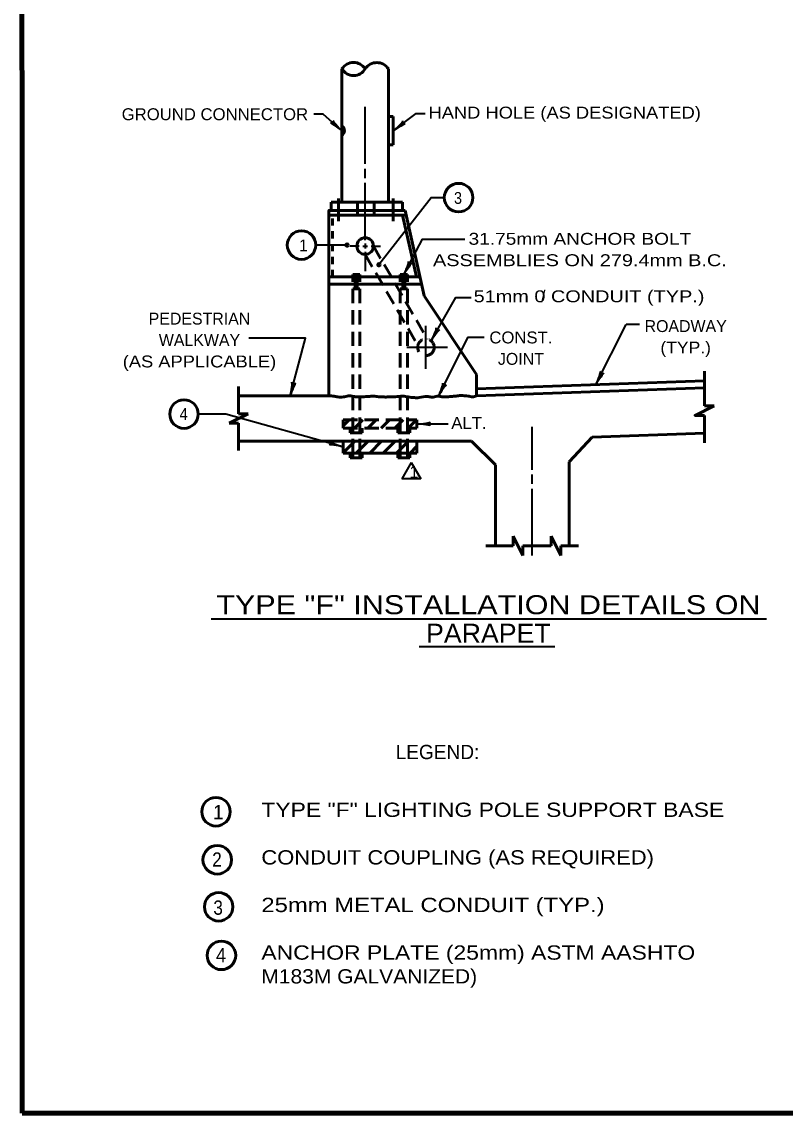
# Model space of a CAD drawing. Extents: x -40 to 816, y -10 to 535.
# Drawn here: x 17.6 to 210.2, y 2 to 277.2 of the extents above; entities that cross this region are included whole.
import ezdxf
from ezdxf.enums import TextEntityAlignment as Align

# ---------------------------------------------------------------- set-up
doc = ezdxf.new("R2010")
doc.units = 0
doc.header["$LTSCALE"] = 1.2
doc.linetypes.add('MEDIUM_DASHED', pattern=[4.5, 3, -1.5])
doc.linetypes.add('SHORT_DASHED', pattern=[2.7, 1.5, -1.2])
doc.layers.add('1', color=7, linetype='Continuous', lineweight=53)

msp = doc.modelspace()

# ---------------------------------------------------------------- hatches: boundary and pattern name
at = {"layer": '1'}
for points in [[(99.956, 220.934, 1), (99.356, 220.934, 1)], [(107.993, 215.956, 1), (107.393, 215.956, 1)]]:
    msp.add_hatch(color=256, dxfattribs=at).paths.add_polyline_path(points)

# ---------------------------------------------------------------- linework, layer by layer
for p, q in [((98.368, 265.381), (98.368, 231.781)), ((110.068, 265.381), (110.068, 231.781)), ((110.068, 253.381), (111.268, 253.381)), ((111.268, 253.381), (111.268, 246.181)), ((110.068, 246.181), (111.268, 246.181)), ((95.668, 231.781), (113.668, 231.781)), ((95.668, 231.781), (95.668, 229.681)), ((97.468, 232.681), (97.468, 226.981)), ((111.268, 232.681), (111.268, 226.981)), ((113.668, 231.781), (113.668, 229.681)), ((95.068, 228.481), (114.539, 228.481)), ((102.268, 229.681), (102.268, 228.481)), ((106.468, 229.681), (106.468, 228.481)), ((113.616, 228.481), (117.138, 212.881)), ((114.268, 229.681), (119.128, 208.155)), ((95.068, 212.881), (118.061, 212.881)), ((101.368, 212.281), (102.568, 212.281)), ((101.668, 213.181), (102.268, 213.181)), ((101.668, 212.581), (102.268, 212.581)), ((101.668, 211.981), (102.268, 211.981)), ((113.368, 212.281), (114.568, 212.281)), ((113.668, 213.181), (114.268, 213.181)), ((113.668, 212.581), (114.268, 212.581)), ((113.668, 211.981), (114.268, 211.981)), ((95.068, 211.081), (118.468, 211.081)), ((101.068, 209.881), (102.868, 209.881)), ((101.368, 211.681), (102.568, 211.681)), ((101.368, 210.481), (102.568, 210.481)), ((101.668, 211.381), (102.268, 211.381)), ((101.668, 210.781), (102.268, 210.781)), ((101.668, 210.181), (102.268, 210.181)), ((113.068, 209.881), (114.868, 209.881)), ((113.368, 211.681), (114.568, 211.681)), ((113.368, 210.481), (114.568, 210.481)), ((113.668, 211.381), (114.268, 211.381)), ((113.668, 210.781), (114.268, 210.781)), ((113.668, 210.181), (114.268, 210.181)), ((119.128, 208.155), (132.268, 188.281)), ((132.268, 182.881), (132.268, 188.281)), ((189.833, 184.891), (189.833, 189.092)), ((72.268, 185.281), (72.268, 178.381)), ((132.268, 184.682), (189.833, 186.692)), ((132.268, 182.881), (189.833, 184.891)), ((189.833, 180.388), (189.833, 184.891)), ((192.233, 180.388), (189.833, 180.388)), ((69.868, 175.981), (74.668, 178.381)), ((74.668, 178.381), (72.268, 178.381)), ((98.668, 175.354), (100.195, 176.881)), ((101.489, 174.781), (103.589, 176.881)), ((104.883, 174.781), (106.983, 176.881)), ((108.277, 174.781), (110.377, 176.881)), ((111.671, 174.781), (113.771, 176.881)), ((115.065, 174.781), (117.165, 176.881)), ((72.268, 175.981), (69.868, 175.981)), ((72.268, 175.981), (72.268, 169.081)), ((161.448, 172.493), (189.833, 173.484)), ((72.268, 171.481), (131.068, 171.481)), ((98.668, 171.481), (98.668, 168.481)), ((98.668, 168.566), (101.583, 171.481)), ((101.977, 168.481), (104.977, 171.481)), ((105.371, 168.481), (108.371, 171.481)), ((108.765, 168.481), (111.765, 171.481)), ((112.159, 168.481), (115.159, 171.481)), ((117.268, 171.481), (117.268, 168.481)), ((131.068, 171.481), (137.068, 165.481)), ((161.448, 172.493), (155.661, 166.287)), ((98.668, 168.481), (117.268, 168.481)), ((100.468, 168.481), (100.468, 167.281)), ((101.068, 168.481), (101.068, 167.281)), ((102.868, 168.481), (102.868, 167.281)), ((103.468, 168.481), (103.468, 167.281)), ((112.468, 168.481), (112.468, 167.281)), ((113.068, 168.481), (113.068, 167.281)), ((114.868, 168.481), (114.868, 167.281)), ((115.468, 168.481), (115.468, 167.281)), ((115.553, 168.481), (117.268, 170.195)), ((100.468, 167.281), (103.468, 167.281)), ((112.468, 167.281), (115.468, 167.281)), ((137.068, 165.481), (137.068, 145.081)), ((155.661, 166.287), (155.661, 145.081)), ((141.564, 147.481), (141.564, 145.081)), ((141.564, 147.481), (143.964, 142.681)), ((151.164, 145.081), (151.164, 147.481)), ((151.164, 147.481), (153.564, 142.681)), ((134.668, 145.081), (141.564, 145.081)), ((143.964, 145.081), (143.964, 142.681)), ((153.564, 142.681), (153.564, 145.081)), ((153.564, 145.081), (158.061, 145.081))]:
    msp.add_line(p, q, dxfattribs=at)
at = {"layer": '1', "lineweight": 35}
for p, q in [((104.218, 241.381), (104.218, 255.781)), ((104.218, 237.781), (104.218, 240.181)), ((104.218, 222.181), (104.218, 236.581)), ((99.656, 220.934), (91.756, 220.923)), ((102.718, 220.681), (100.318, 220.681)), ((103.618, 220.681), (104.818, 220.681)), ((104.218, 221.281), (104.218, 220.081)), ((162.446, 185.736), (170.051, 200.9)), ((173.452, 200.9), (170.051, 200.9)), ((117.268, 175.831), (125.171, 175.831)), ((146.364, 164.281), (146.364, 175.081)), ((115.847, 166.117), (113.447, 161.96)), ((115.847, 166.117), (118.247, 161.96)), ((146.364, 160.681), (146.364, 163.081)), ((118.247, 161.96), (113.447, 161.96)), ((146.364, 142.681), (146.364, 159.481))]:
    msp.add_line(p, q, dxfattribs=at)
at = {"layer": '1', "linetype": 'SHORT_DASHED'}
for p, q in [((102.268, 231.781), (102.268, 229.681)), ((106.468, 231.781), (106.468, 229.681)), ((95.968, 212.881), (95.968, 228.481))]:
    msp.add_line(p, q, dxfattribs=at)
at = {"layer": '1', "linetype": 'MEDIUM_DASHED'}
for p, q in [((106.318, 220.681), (119.879, 197.215)), ((104.218, 218.581), (117.503, 195.592)), ((101.068, 168.481), (101.068, 213.481)), ((101.068, 213.481), (102.868, 213.481)), ((102.868, 168.481), (102.868, 213.481)), ((113.068, 168.481), (113.068, 213.481)), ((113.068, 213.481), (114.868, 213.481)), ((113.068, 212.881), (114.868, 212.881)), ((114.868, 168.481), (114.868, 213.481)), ((113.068, 211.081), (114.868, 211.081)), ((98.668, 176.881), (117.268, 176.881)), ((98.668, 176.881), (98.668, 174.781)), ((117.268, 176.881), (117.268, 174.781)), ((98.668, 174.781), (117.268, 174.781)), ((100.468, 173.581), (100.468, 174.781)), ((100.468, 173.581), (103.468, 173.581)), ((103.468, 173.581), (103.468, 174.781)), ((112.468, 173.581), (112.468, 174.781)), ((112.468, 173.581), (115.468, 173.581)), ((115.468, 173.581), (115.468, 174.781))]:
    msp.add_line(p, q, dxfattribs=at)
at = {"layer": '1', "lineweight": 40}
for p, q in [((65.365, 126.637), (205.457, 126.637)), ((117.867, 119.737), (152.044, 119.737))]:
    msp.add_line(p, q, dxfattribs=at)
at = {"layer": '1', "lineweight": 158}
msp.add_line((809.296, 2.017), (17.696, 2.017), dxfattribs=at)
msp.add_lwpolyline([(809.296, 528.117), (17.596, 528.017), (17.696, 2.017)], dxfattribs=at)
at = {"layer": '1', "lineweight": 35}
for points in [[(98.368, 249.74), (93.63, 253.914), (91.242, 253.914)], [(111.268, 249.728), (117.125, 254.136), (119.347, 254.136)], [(107.635, 215.986), (120.873, 232.891), (124.184, 232.891)], [(105.718, 220.681), (106.318, 220.681), (108.118, 220.681)], [(113.975, 213.481), (118.714, 222.437), (129.397, 222.437)], [(104.218, 219.181), (104.218, 218.581), (104.218, 214.381)], [(120.874, 196.774), (127.086, 207.723), (130.964, 207.723)], [(119.554, 189.74), (119.554, 197.24), (119.554, 200.541)], [(85.307, 182.881), (89.155, 197.409), (74.908, 197.409)], [(122.722, 182.812), (130.207, 197.693), (134.275, 197.693)], [(114.754, 195.141), (117.454, 195.141), (124.954, 195.141)], [(98.569, 170.027), (69.074, 178.308), (62.116, 178.308)]]:
    msp.add_lwpolyline(points, dxfattribs=at)
at = {"layer": '1'}
for points in [[(72.268, 182.881), (95.068, 182.881), (95.068, 229.681), (114.268, 229.681)], [(189.833, 177.988), (187.433, 177.988), (192.233, 180.388)], [(189.833, 171.084), (189.833, 173.484), (189.833, 177.988)], [(143.964, 145.081), (146.364, 145.081), (151.164, 145.081)]]:
    msp.add_lwpolyline(points, dxfattribs=at)
for centre, radius in [((127.784, 232.891), 3.6), ((88.156, 220.923), 3.6), ((99.656, 220.934), 0.3), ((104.218, 220.681), 2.1), ((107.693, 215.956), 0.3), ((58.516, 178.308), 3.6), ((66.582, 78.028), 3.6), ((66.905, 65.909), 3.6), ((67.254, 54.052), 3.6), ((67.954, 41.808), 3.6)]:
    msp.add_circle(centre, radius, dxfattribs=at)
at = {"layer": '1', "linetype": 'MEDIUM_DASHED'}
msp.add_circle((119.554, 195.141), 2.1, dxfattribs=at)
at = {"layer": '1'}
for centre, radius, start, end in [((101.293, 263.531), 3.461, 32.30565, 147.69435), ((101.293, 267.057), 3.381, 210.08876, 329.91124), ((107.143, 263.429), 3.516, 33.70919, 146.29081), ((97.468, 249.781), 1.5, 306.8699, 53.1301)]:
    msp.add_arc(centre, radius, start, end, dxfattribs=at)
at = {"layer": '1', "lineweight": 40}
for centre, major_axis, ratio, start_param, end_param in [((97.166, 250.356), (1.732, -1.276), 0.122415, 0.8963533, 3.1415927), ((97.527, 250.819), (-1.442, 1.552), 0.07063, 6.2823074, 8.5597026), ((112.114, 250.78), (-1.599, -1.438), 0.122415, 0.8963533, 3.1415927), ((112.495, 250.333), (1.811, 1.099), 0.07063, 6.2823074, 8.5597026), ((114.294, 214.793), (-0.837, -1.982), 0.122415, 0.8963533, 3.1415927), ((114.828, 214.551), (1.172, 1.764), 0.07063, 6.2823074, 8.5597026), ((121.231, 198.077), (-0.894, -1.956), 0.122415, 0.8963533, 3.1415927), ((121.758, 197.818), (1.223, 1.729), 0.07063, 6.2823074, 8.5597026), ((162.737, 187.055), (-0.793, -1.999), 0.122415, 0.8963533, 3.1415927), ((163.276, 186.824), (-1.133, -1.79), 0.07063, 3.1407148, 5.41811), ((85.322, 184.232), (-0.367, -2.119), 0.122415, 0.8963533, 3.1415927), ((85.897, 184.116), (-0.743, -1.984), 0.07063, 3.1407148, 5.41811), ((123.014, 184.131), (-0.796, -1.998), 0.122415, 0.8963533, 3.1415927), ((123.553, 183.899), (1.135, 1.788), 0.07063, 6.2823074, 8.5597026), ((118.577, 176.162), (-2.143, -0.187), 0.122415, 0.8963533, 3.1415927), ((118.612, 175.577), (-2.108, 0.211), 0.07063, 3.1407148, 5.41811), ((97.343, 170.635), (-1.972, 0.773), 0.07063, 6.2823074, 8.5597026), ((97.219, 170.062), (2.114, -0.399), 0.122415, 0.8963533, 3.1415927)]:
    msp.add_ellipse(centre, major_axis=major_axis, ratio=ratio, start_param=start_param, end_param=end_param, dxfattribs=at)
at = {"layer": '1'}
msp.add_spline([(95.068, 182.881), (96.419, 182.812), (97.284, 182.655), (97.992, 182.576), (98.739, 182.615), (99.014, 182.655), (99.682, 182.851), (100.586, 182.891), (101.333, 182.773), (102.237, 182.655), (103.141, 182.694), (103.967, 182.694), (104.753, 182.773), (105.421, 182.773), (106.325, 182.812), (107.583, 182.655), (108.802, 182.615), (109.745, 182.615), (110.61, 182.655), (111.907, 182.694), (112.694, 182.733), (113.755, 182.812), (115.091, 182.615), (116.625, 182.458), (117.843, 182.458), (119.809, 182.733), (120.398, 182.655), (121.381, 182.576), (122.718, 182.812), (123.543, 182.694), (124.604, 182.655), (125.902, 182.733), (127.16, 182.851), (128.339, 182.969), (129.439, 182.93), (130.186, 182.851), (131.287, 182.655), (132.268, 182.881)], degree=3, dxfattribs=at)

# ---------------------------------------------------------------- texts
for s, height, width, p in [('HAND HOLE (AS DESIGNATED)', 3, 1.15, (154.563, 252.828)), ('GROUND CONNECTOR', 3, 1.05, (66.308, 252.418)), ('3', 3, 0.9, (127.643, 231.306)), ('31.75mm ANCHOR BOLT', 3, 1.2, (158.393, 221.004)), ('ASSEMBLIES ON 279.4mm B.C.', 3, 1.25, (158.393, 215.604)), ('51mm 0 CONDUIT (TYP.)', 3, 1.25, (160.694, 206.508)), ('CONST.', 3, 1.05, (143.505, 196.126)), ('(TYP.)', 3, 1.1, (185.073, 193.593)), ('(AS APPLICABLE)', 3, 1.15, (62.417, 190.074)), ('4', 3, 0.95, (58.436, 176.834)), ('ALT.', 3, 1.05, (130.4, 174.581)), ('TYPE "F" INSTALLATION DETAILS ON', 4.8, 1.2, (135.304, 127.837)), ('PARAPET', 4.8, 1.05, (135.304, 120.637)), ('2', 3.6, 0.9, (66.831, 64.167)), ('3', 3.6, 0.9, (67.123, 52.048)), ('4', 3.6, 0.95, (67.853, 40.075))]:
    msp.add_text(s, height=height, dxfattribs=dict(at, width=width)).set_placement(p, align=Align.CENTER)
for s, height, p in [('1', 3, (88.642, 219.321)), ('/', 3, (149.168, 206.555)), ('PEDESTRIAN', 3, (62.417, 200.874)), ('ROADWAY', 3, (185.073, 198.993)), ('WALKWAY', 3, (62.417, 195.474)), ('JOINT', 3, (143.505, 190.726)), ('1', 3, (116.53, 162.227)), ('LEGEND:', 3.6, (122.465, 91.296)), ('1', 3.6, (67.173, 76.14))]:
    msp.add_text(s, height=height, dxfattribs=at).set_placement(p, align=Align.CENTER)
for s, width, p in [('TYPE "F" LIGHTING POLE SUPPORT BASE', 1.2, (78.026, 76.724)), ('CONDUIT COUPLING (AS REQUIRED)', 1.15, (78.026, 64.724)), ('25mm METAL CONDUIT (TYP.)', 1.25, (78.026, 52.724)), ('ANCHOR PLATE (25mm) ASTM AASHTO', 1.2, (78.026, 40.724)), ('M183M GALVANIZED)', 1.1, (78.026, 34.724))]:
    msp.add_text(s, height=3.6, dxfattribs=dict(at, width=width)).set_placement(p)

doc.saveas('drawing.dxf')
